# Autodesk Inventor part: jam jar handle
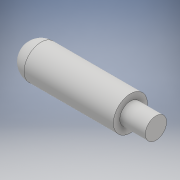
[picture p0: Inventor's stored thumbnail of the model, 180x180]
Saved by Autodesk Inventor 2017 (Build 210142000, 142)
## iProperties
Created: 2017-02
Part Number: jam jar handle
Material: Generic
Document SubType Name: Modeling
Designer: malcolm
Mass: 10.4594 g
Surface Area: 30.9133 cm^2
Volume: 10.4594 cm^3
Density: 1 g/cm^3
Appearance: Default
Author: malcolm
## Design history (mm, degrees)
sketch "Sketch1"
  geometry: C1 r 8 at (0, 0); 1 further point
  constraints: 1 centre point, 1 coincident
  dimensions: "d0" = 16 diameter of C1
extrude "Extrusion1" new body sketch "Sketch1" distance "d1" = 50; taper "d2" = 0 deg
sketch "Sketch2"
  geometry: C1 r 5 at (0, 0); 1 further point
  constraints: 1 centre point, 1 coincident
  dimensions: "d3" = 10 diameter of C1
extrude "Extrusion2" join sketch "Sketch2" distance "d4" = 12; taper "d5" = 0 deg
fillet "Fillet1" dims "d6" = 8
body "Solid1"
